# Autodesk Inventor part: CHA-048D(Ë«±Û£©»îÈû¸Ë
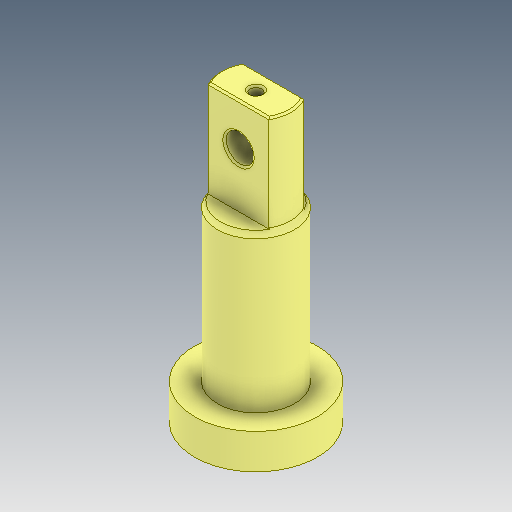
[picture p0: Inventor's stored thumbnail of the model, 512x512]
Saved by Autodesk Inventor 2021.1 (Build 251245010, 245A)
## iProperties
Created: 2021-05
Part Number: CHA-048D(Ë«±Û£©»îÈû¸Ë
Material: Ogólny
Document SubType Name: Modeling
Designer: user
Density: 1 g/cm^3
Appearance: Domyślna
Author: user
Revision Number: ÈÎºÎ
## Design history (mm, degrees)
feature "ÊäÈë1"
node "Bryła1"
